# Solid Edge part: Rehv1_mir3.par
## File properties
Author: KULL
Template: Iso Metric Part.par
Last saved by: KULL
Revision: 2
Application: Solid Edge
Accuracy: 0,990
Username: KULL
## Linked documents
Rehv1.par
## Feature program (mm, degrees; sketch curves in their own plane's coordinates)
part copy "CopiedPart_1"
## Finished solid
Body 1: solid body, 650 faces, 1688 edges, 1040 vertices.
  Faces by surface: spline 520, torus 62, cylinder 54, cone 8, plane 6
  Edges by curve: intersection 1040, line 390, curve on surface 130, circle 128
Bounding box of the edges (mm; curved faces can reach further): 42.451 x 100.967 x 100.966, from (-41.2257, -50.4835, -50.483) to (1.2257, 50.4835, 50.483).
Cylindrical faces by radius (mm): R49.482 x1, R50.082 x52, R50.482 x1
Conical faces (half-angle, radius in mm at the cone's reference point): 14.1898 deg R43.1591 x1, 14.1898 deg R43.6493 x1, 14.1898 deg R44.4434 x1, 14.1898 deg R44.864 x1, 75.8102 deg R41.5194 x1, 75.8102 deg R41.7645 x1, 75.8102 deg R43.6493 x1, 75.8102 deg R44.864 x1
Toroidal faces (ring radius, tube radius in mm): R41.9116 r0.6 x2, R41.9116 r1.6 x2, R43.4159 r0.2 x2, R47.1178 r2.3642 x2, R47.1178 r2.9642 x52, R47.1178 r3.3642 x2
Planar faces by outward normal: +x 3, -x 3
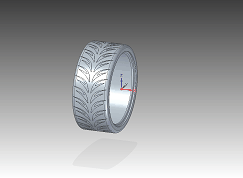
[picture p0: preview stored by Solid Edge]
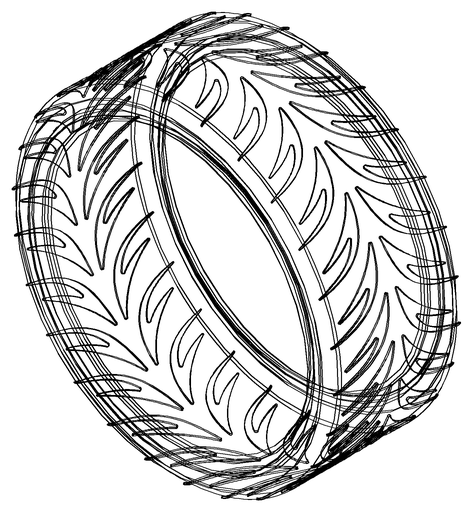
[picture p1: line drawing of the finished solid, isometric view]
